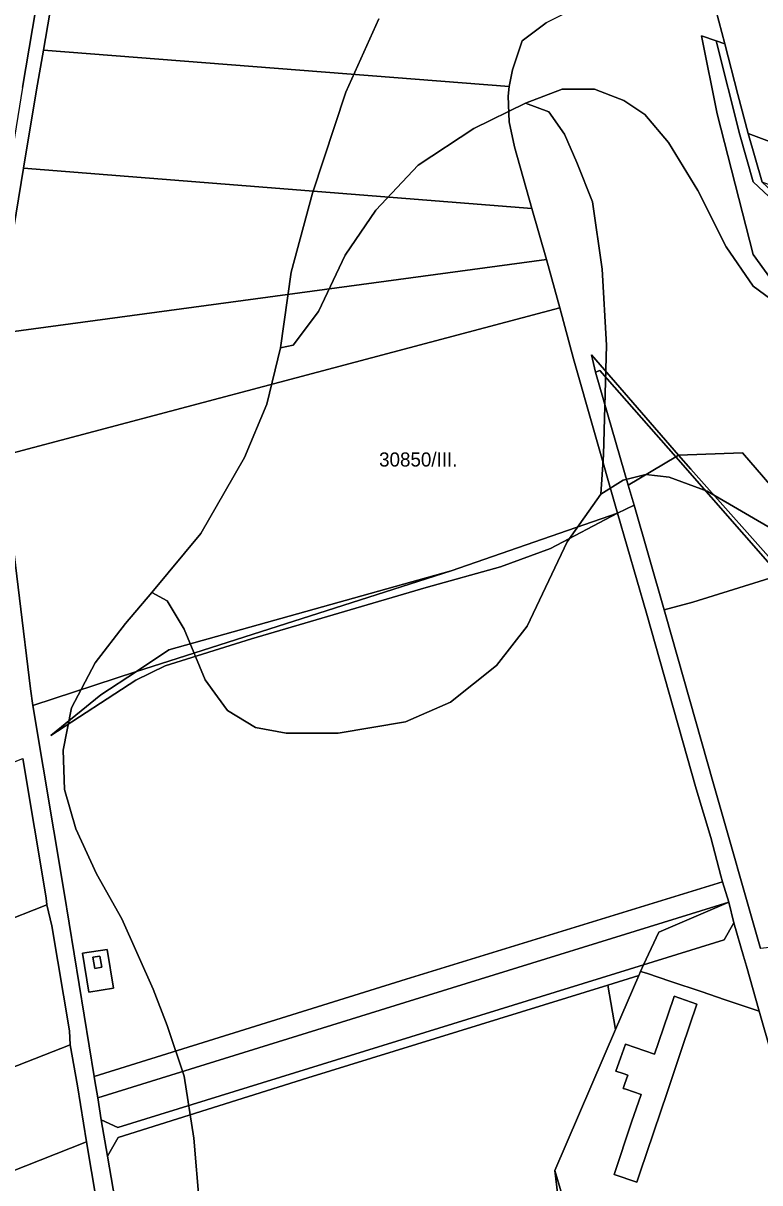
# Model space of a CAD drawing. Extents: x -541351 to -537540, y -1162694 to -1159725.
# Drawn here: x -540378.9 to -540116.8, y -1160827.9 to -1160415.5 of the extents above; entities that cross this region are included whole.
import ezdxf

# ---------------------------------------------------------------- set-up
doc = ezdxf.new("R2010")
doc.units = 0
for name, color, linetype in [('95560013', 7, 'Continuous'), ('95610013', 7, 'Continuous'), ('95640013', 7, 'Continuous'), ('95660013', 7, 'Continuous')]:
    doc.layers.add(name, color=color, linetype=linetype)

msp = doc.modelspace()

# ---------------------------------------------------------------- linework, layer by layer
at = {"layer": '95560013'}
for points in [[(-540527.1, -1160309.52), (-540367.38, -1160369.03), (-540379.07, -1160438.35), (-540385.21, -1160475.93), (-540388.61, -1160496.72), (-540565.8, -1160430.3), (-540549.55, -1160378.18), (-540535.84, -1160336.23)], [(-539919.82, -1160409.86), (-539934.65, -1160497.18), (-539939.3, -1160504.82), (-539943.59, -1160508.57), (-539953.62, -1160517.32), (-540120.93, -1160454.7), (-540124.57, -1160440.83), (-540129.29, -1160422.87), (-540136.74, -1160394.52), (-540133.58, -1160382.33), (-540128.1, -1160326.8), (-540126.4, -1160311.55), (-540100.25, -1160312.92), (-540099.35, -1160311.53), (-540097.45, -1160311.62), (-540018.39, -1160316.26), (-539910.82, -1160357.17), (-539913.57, -1160373.29), (-539923.43, -1160371.6), (-539925.11, -1160381.46), (-539915.26, -1160383.15)], [(-540192.75, -1160415.42), (-540201.36, -1160421.81), (-540204.8, -1160432.12), (-540205.99, -1160438.05), (-540371.68, -1160425.08), (-540361.01, -1160362.65), (-540139.42, -1160379.64), (-540139.64, -1160380.67), (-540142.35, -1160391.33), (-540147.64, -1160399.81), (-540156.43, -1160404.54), (-540167.21, -1160406.8), (-540175.62, -1160408.05), (-540184.29, -1160411.12)], [(-540197.95, -1160481.47), (-540378.74, -1160467.09), (-540374.16, -1160439.26), (-540371.68, -1160425.08), (-540205.99, -1160438.05), (-540206.38, -1160441.43), (-540206.02, -1160450.55), (-540204.09, -1160459.51)], [(-540115.93, -1160472.05), (-540120.93, -1160454.7), (-539953.62, -1160517.32), (-539965.88, -1160527.52)], [(-540378.74, -1160467.09), (-540197.95, -1160481.47), (-540192.63, -1160499.6), (-540388.47, -1160525.94)], [(-540390.49, -1160537.06), (-540388.47, -1160525.94), (-540192.63, -1160499.6), (-540187.97, -1160516.78), (-540287.54, -1160543.17), (-540386.78, -1160569.5)], [(-540287.54, -1160543.17), (-540187.97, -1160516.78), (-540183.04, -1160534.82), (-540167.89, -1160588.16), (-540167.37, -1160589.73), (-540226.63, -1160610.28), (-540327.01, -1160638.37), (-540338.61, -1160646.06), (-540375.43, -1160658.17), (-540376.23, -1160652.23), (-540384.15, -1160587.81), (-540386.78, -1160569.5)], [(-540175.24, -1160539.58), (-540176.71, -1160533.49), (-540145.68, -1160569.15), (-540146.72, -1160569.77), (-540173.72, -1160539.05)], [(-540163.58, -1160579.77), (-540175.24, -1160539.58), (-540173.72, -1160539.05), (-540146.72, -1160569.77)], [(-540375.43, -1160658.17), (-540338.61, -1160646.06), (-540351.22, -1160654.42), (-540369.07, -1160668.8), (-540338.81, -1160649.12), (-540328.37, -1160644.12), (-540297.65, -1160634.43), (-540235.46, -1160616.26), (-540209.03, -1160608.9), (-540191.32, -1160602.39), (-540167.37, -1160589.73), (-540157.08, -1160625.32), (-540139.42, -1160687.77), (-540134.18, -1160705.08), (-540130.64, -1160718.79), (-540130.05, -1160720.87), (-540242.63, -1160755.45), (-540353.65, -1160790.09), (-540364.34, -1160724.7)], [(-540239.65, -1160762.78), (-540352.31, -1160797.72), (-540353.36, -1160791.66), (-540353.65, -1160790.09), (-540242.63, -1160755.45), (-540130.05, -1160720.87), (-540127.86, -1160728.09)], [(-540362.13, -1160778.82), (-540540.33, -1160848.73), (-540544.72, -1160800.38), (-540544.91, -1160797.79), (-540370.43, -1160729.11), (-540368.65, -1160736.51), (-540362.4, -1160773.82)], [(-540351.12, -1160805.53), (-540352.31, -1160797.72), (-540239.65, -1160762.78), (-540127.86, -1160728.09), (-540152.74, -1160738.76), (-540158.12, -1160750.38), (-540345.21, -1160808.22)], [(-540357.81, -1160746.26), (-540355.54, -1160760.09), (-540346.71, -1160758.68), (-540349.01, -1160744.97)], [(-540159.21, -1160752.73), (-540159.87, -1160754.25), (-540170.82, -1160757.62), (-540277.65, -1160790.58), (-540345.13, -1160811.78), (-540348.88, -1160818.39), (-540351.12, -1160805.53), (-540345.21, -1160808.22), (-540158.12, -1160750.38)], [(-540159.87, -1160754.25), (-540168.1, -1160773.35), (-540170.82, -1160757.62)], [(-540168.1, -1160773.35), (-540189.73, -1160823.53), (-540186.01, -1160854.27), (-540193.55, -1160916.96), (-540251.03, -1160920.53), (-540309.4, -1160924.39), (-540325.44, -1160925.28), (-540331.73, -1160920.05), (-540342.08, -1160857.75), (-540348.88, -1160818.39), (-540345.13, -1160811.78), (-540277.65, -1160790.58), (-540170.82, -1160757.62)], [(-540356.38, -1160813.29), (-540536.65, -1160884.54), (-540538.58, -1160865.14), (-540540.33, -1160848.73), (-540362.13, -1160778.82), (-540359.51, -1160793.49)], [(-540352.78, -1160834.49), (-540351.34, -1160843.57), (-540533.54, -1160915.14), (-540534.55, -1160905.79), (-540536.65, -1160884.54), (-540356.38, -1160813.29)]]:
    msp.add_lwpolyline(points, close=True, dxfattribs=at)
for points in [[(-540136.74, -1160394.52), (-540129.29, -1160422.87), (-540132.3, -1160421.84), (-540137.57, -1160420.03), (-540131.98, -1160447.76), (-540119.13, -1160497.83), (-540078.88, -1160553.44)], [(-540090.77, -1160605.52), (-540122.99, -1160568.3), (-540145.68, -1160569.15), (-540176.71, -1160533.49), (-540175.24, -1160539.58), (-540163.58, -1160579.77), (-540161.5, -1160586.91), (-540167.37, -1160589.73), (-540167.89, -1160588.16), (-540183.04, -1160534.82), (-540187.97, -1160516.78), (-540192.63, -1160499.6), (-540197.95, -1160481.47), (-540204.09, -1160459.51), (-540206.02, -1160450.55), (-540206.38, -1160441.43), (-540205.99, -1160438.05), (-540204.8, -1160432.12), (-540201.36, -1160421.81), (-540192.75, -1160415.42)]]:
    msp.add_lwpolyline(points, dxfattribs=at)
at = {"layer": '95610013'}
for points in [[(-540078.88, -1160553.44), (-540119.13, -1160497.83), (-540131.98, -1160447.76), (-540137.57, -1160420.03), (-540132.3, -1160421.84), (-540123.88, -1160455.21), (-540119.18, -1160471.96), (-540055.96, -1160531.12)], [(-540107.96, -1160611.59), (-540141.33, -1160574.15), (-540145.68, -1160569.15), (-540122.99, -1160568.3), (-540090.77, -1160605.52)]]:
    msp.add_lwpolyline(points, dxfattribs=at)
for points in [[(-540161.5, -1160586.91), (-540163.58, -1160579.77), (-540146.72, -1160569.77), (-540109.81, -1160611.78), (-540140.65, -1160621.39), (-540150.87, -1160624.16)], [(-540167.37, -1160589.73), (-540191.32, -1160602.39), (-540209.03, -1160608.9), (-540235.46, -1160616.26), (-540297.65, -1160634.43), (-540328.37, -1160644.12), (-540338.81, -1160649.12), (-540369.07, -1160668.8), (-540351.22, -1160654.42), (-540338.61, -1160646.06), (-540226.63, -1160610.28)], [(-540338.61, -1160646.06), (-540327.01, -1160638.37), (-540226.63, -1160610.28)], [(-540116.53, -1160744.57), (-540133.22, -1160686.01), (-540150.39, -1160625.84), (-540150.87, -1160624.16), (-540140.65, -1160621.39), (-540109.81, -1160611.78), (-540108.07, -1160613.76), (-540107.83, -1160614.04), (-540067.41, -1160659.58), (-540072.96, -1160663.43), (-540059.03, -1160692.85), (-540036.88, -1160735.75)], [(-540370.76, -1160726.58), (-540370.43, -1160729.11), (-540544.91, -1160797.79), (-540549.68, -1160743.9), (-540379.03, -1160677.01)], [(-540158.12, -1160750.38), (-540152.74, -1160738.76), (-540127.86, -1160728.09), (-540125.99, -1160735.41), (-540129.5, -1160741.53)], [(-540157.05, -1160753.39), (-540159.21, -1160752.73), (-540158.12, -1160750.38), (-540129.5, -1160741.53), (-540125.99, -1160735.41), (-540122.56, -1160747.33), (-540121.54, -1160750.93), (-540117.04, -1160766.9), (-540129.12, -1160762.82), (-540137.65, -1160759.94), (-540148.41, -1160756.31)], [(-540185.88, -1160909.3), (-540171.5, -1160915.74), (-540193.55, -1160916.96), (-540186.01, -1160854.27), (-540189.73, -1160823.53), (-540183.69, -1160843.89), (-540155.41, -1160846.86), (-540140.76, -1160848.4), (-540132.39, -1160849.28), (-540130.65, -1160849.46), (-540131.83, -1160852.51), (-540137.54, -1160867.19), (-540147.48, -1160892.81), (-540156.04, -1160914.84), (-540162.89, -1160915.22), (-540168.92, -1160915.58), (-540157.78, -1160895.24), (-540174.66, -1160887.93)]]:
    msp.add_lwpolyline(points, close=True, dxfattribs=at)
at = {"layer": '95640013'}
for points in [[(-540361.01, -1160362.65), (-540371.68, -1160425.08), (-540374.16, -1160439.26), (-540378.74, -1160467.09), (-540388.47, -1160525.94)], [(-540379.07, -1160438.35), (-540367.38, -1160369.03)], [(-540090.94, -1160857.78), (-540117.04, -1160766.9), (-540121.54, -1160750.93), (-540122.56, -1160747.33), (-540125.99, -1160735.41), (-540127.86, -1160728.09), (-540130.05, -1160720.87), (-540130.64, -1160718.79), (-540134.18, -1160705.08), (-540139.42, -1160687.77), (-540157.08, -1160625.32), (-540167.37, -1160589.73), (-540161.5, -1160586.91), (-540150.87, -1160624.16), (-540150.39, -1160625.84), (-540133.22, -1160686.01), (-540116.53, -1160744.57)], [(-540384.15, -1160587.81), (-540376.23, -1160652.23), (-540375.43, -1160658.17), (-540364.34, -1160724.7), (-540353.65, -1160790.09), (-540353.36, -1160791.66), (-540352.31, -1160797.72), (-540351.12, -1160805.53), (-540348.88, -1160818.39), (-540342.08, -1160857.75)], [(-540352.78, -1160834.49), (-540356.38, -1160813.29), (-540359.51, -1160793.49), (-540362.13, -1160778.82), (-540362.4, -1160773.82), (-540368.65, -1160736.51), (-540370.43, -1160729.11), (-540370.76, -1160726.58), (-540379.03, -1160677.01)], [(-540183.69, -1160843.89), (-540189.73, -1160823.53), (-540168.1, -1160773.35), (-540159.87, -1160754.25), (-540159.21, -1160752.73), (-540157.05, -1160753.39), (-540148.41, -1160756.31), (-540137.65, -1160759.94), (-540129.12, -1160762.82), (-540117.04, -1160766.9), (-540090.94, -1160857.78)]]:
    msp.add_lwpolyline(points, dxfattribs=at)
for points in [[(-540053.98, -1160529.34), (-540055.96, -1160531.12), (-540119.18, -1160471.96), (-540123.88, -1160455.21), (-540132.3, -1160421.84), (-540129.29, -1160422.87), (-540124.57, -1160440.83), (-540120.93, -1160454.7), (-540115.93, -1160472.05)], [(-540109.81, -1160611.78), (-540146.72, -1160569.77), (-540145.68, -1160569.15), (-540141.33, -1160574.15), (-540107.96, -1160611.59), (-540065.89, -1160658.49), (-540067.41, -1160659.58), (-540107.83, -1160614.04), (-540108.07, -1160613.76)], [(-540357.81, -1160746.26), (-540349.01, -1160744.97), (-540346.71, -1160758.68), (-540355.54, -1160760.09)], [(-540351.63, -1160747.27), (-540350.95, -1160751.27), (-540353.42, -1160751.69), (-540354.09, -1160747.63)], [(-540351.63, -1160747.27), (-540354.09, -1160747.63), (-540353.42, -1160751.69), (-540350.95, -1160751.27)], [(-540139.14, -1160764.33), (-540144.36, -1160779.8), (-540149.77, -1160795.83), (-540159.33, -1160824.15), (-540160.53, -1160827.69), (-540168.65, -1160824.95), (-540162.39, -1160806.41), (-540159.04, -1160796.48), (-540164.42, -1160794.67), (-540165.41, -1160794.34), (-540164.78, -1160792.6), (-540163.71, -1160789.66), (-540165.38, -1160789.1), (-540167.98, -1160788.23), (-540166.32, -1160783.65), (-540164.52, -1160778.67), (-540154.2, -1160782.14), (-540152.82, -1160778.05), (-540147.42, -1160762.04), (-540147.27, -1160761.59)], [(-540159.33, -1160824.15), (-540149.77, -1160795.83), (-540144.36, -1160779.8), (-540139.14, -1160764.33), (-540147.27, -1160761.59), (-540147.42, -1160762.04), (-540152.82, -1160778.05), (-540154.2, -1160782.14), (-540164.52, -1160778.67), (-540166.32, -1160783.65), (-540167.98, -1160788.23), (-540165.38, -1160789.1), (-540163.71, -1160789.66), (-540164.78, -1160792.6), (-540165.41, -1160794.34), (-540164.42, -1160794.67), (-540159.04, -1160796.48), (-540162.39, -1160806.41), (-540168.65, -1160824.95), (-540160.53, -1160827.69)]]:
    msp.add_lwpolyline(points, close=True, dxfattribs=at)
at = {"layer": '95660013'}
for points in [[(-540252.37, -1160414), (-540264.12, -1160440), (-540276, -1160476), (-540283.5, -1160504), (-540287.31, -1160531), (-540292.19, -1160551), (-540300.19, -1160570), (-540307.05, -1160582), (-540315.62, -1160597), (-540333.12, -1160618), (-540342.5, -1160629), (-540353.31, -1160643), (-540361.69, -1160659), (-540364.69, -1160674), (-540364.19, -1160688), (-540360.19, -1160702), (-540352.81, -1160718), (-540343.81, -1160734), (-540332.62, -1160759), (-540327.62, -1160772), (-540321.62, -1160790), (-540318.12, -1160812), (-540316.12, -1160836)], [(-540111.12, -1160515), (-540119.12, -1160509), (-540128.81, -1160495), (-540138.81, -1160475), (-540149.31, -1160458), (-540157.69, -1160448), (-540165.19, -1160443), (-540169.83, -1160441.22), (-540175.62, -1160439), (-540187.12, -1160439), (-540200.12, -1160444), (-540218.5, -1160453), (-540238.37, -1160466), (-540253.37, -1160482), (-540264.31, -1160498), (-540273.81, -1160518), (-540282.81, -1160530), (-540287.31, -1160531), (-540283.5, -1160504), (-540276, -1160476), (-540264.12, -1160440), (-540252.37, -1160414)], [(-540109.62, -1160597), (-540135.5, -1160582), (-540149, -1160577), (-540157.37, -1160576), (-540165.37, -1160578), (-540173.37, -1160583), (-540172.37, -1160569), (-540171.37, -1160530), (-540172.87, -1160503), (-540176.37, -1160479), (-540181.87, -1160465), (-540186.31, -1160455), (-540191.81, -1160447), (-540200.12, -1160444), (-540187.12, -1160439), (-540175.62, -1160439), (-540169.83, -1160441.22), (-540165.19, -1160443), (-540157.69, -1160448), (-540149.31, -1160458), (-540138.81, -1160475), (-540128.81, -1160495), (-540119.12, -1160509), (-540111.12, -1160515)], [(-540316.12, -1160836), (-540318.12, -1160812), (-540321.62, -1160790), (-540327.62, -1160772), (-540332.62, -1160759), (-540343.81, -1160734), (-540352.81, -1160718), (-540360.19, -1160702), (-540364.19, -1160688), (-540364.69, -1160674), (-540361.69, -1160659), (-540353.31, -1160643), (-540342.5, -1160629), (-540333.12, -1160618), (-540327.62, -1160621), (-540321.62, -1160631), (-540314.12, -1160649), (-540309.71, -1160655.11), (-540306.19, -1160660), (-540296.19, -1160666), (-540285.31, -1160668), (-540266.81, -1160668), (-540242.87, -1160664), (-540226.87, -1160657), (-540210.5, -1160644), (-540199.62, -1160630), (-540185.31, -1160600), (-540173.37, -1160583), (-540165.37, -1160578), (-540157.37, -1160576), (-540149, -1160577), (-540135.5, -1160582), (-540109.62, -1160597)]]:
    msp.add_lwpolyline(points, dxfattribs=at)
msp.add_lwpolyline([(-540173.37, -1160583), (-540185.31, -1160600), (-540199.62, -1160630), (-540210.5, -1160644), (-540226.87, -1160657), (-540242.87, -1160664), (-540266.81, -1160668), (-540285.31, -1160668), (-540296.19, -1160666), (-540306.19, -1160660), (-540309.71, -1160655.11), (-540314.12, -1160649), (-540321.62, -1160631), (-540327.62, -1160621), (-540333.12, -1160618), (-540315.62, -1160597), (-540307.05, -1160582), (-540300.19, -1160570), (-540292.19, -1160551), (-540287.31, -1160531), (-540282.81, -1160530), (-540273.81, -1160518), (-540264.31, -1160498), (-540253.37, -1160482), (-540238.37, -1160466), (-540218.5, -1160453), (-540200.12, -1160444), (-540191.81, -1160447), (-540186.31, -1160455), (-540181.87, -1160465), (-540176.37, -1160479), (-540172.87, -1160503), (-540171.37, -1160530), (-540172.37, -1160569)], close=True, dxfattribs=at)

# ---------------------------------------------------------------- texts
msp.add_text('30850/III.', height=5, rotation=360, dxfattribs=at).set_placement((-540252.25, -1160573.18))

doc.saveas('drawing.dxf')
